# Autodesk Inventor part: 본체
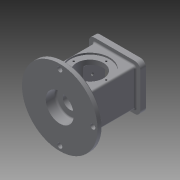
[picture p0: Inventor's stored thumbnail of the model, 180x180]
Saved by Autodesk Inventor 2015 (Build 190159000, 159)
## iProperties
Created: 2019-08
Part Number: 본체
Material: 일반
Document SubType Name: Modeling
Designer: a3
Density: 1 g/cm^3
Appearance: 기본값
Author: a3
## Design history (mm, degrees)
sketch "스케치1"
  geometry: L1 (37, 33)-(-37, 33); L2 (-37, 33)-(-37, -33); L3 (-37, -33)-(37, -33); L4 (37, -33)-(37, 33); 1 further point
  constraints: 8 end point, 2 parallel, 1 horizontal, 1 perpendicular
  dimensions: "d0" = 66 distance of L3.end L1.start; "d1" = 74 distance of L1.start L1.end; "d3" = 37 distance from line of point (0, 0) L4; "d15" = 33 distance from line of point (0, 0) L3
extrude "돌출1" new body sketch "스케치1" stored distance "d4" = 108; taper "d5" = 0 deg
sketch "스케치2"
  geometry: L1 (37, 33)-(-37, 33) reference; L2 (-37, 33)-(-37, -33) reference; L3 (-37, -33)-(37, -33) reference; L4 (37, -33)-(37, 33) reference; C1 r 67.5 at (0, 0); 1 further point
  constraints: 1 centre point, 1 coincident
  dimensions: "d6" = 135 diameter of C1
extrude "돌출2" join sketch "스케치2" distance "d7" = 10; taper "d8" = 0 deg
sketch "스케치3"
  geometry: L1 (-46, 41)-(46, 41); L2 (46, 41)-(46, -41); L3 (46, -41)-(-46, -41); L4 (-46, -41)-(-46, 41); L5 (-37, -33)-(37, -33) reference; L6 (37, -33)-(37, 33) reference; L7 (37, 33)-(-37, 33) reference; L8 (-37, 33)-(-37, -33) reference; 1 further point
  constraints: 8 end point, 2 parallel, 1 horizontal, 1 perpendicular
  dimensions: "d9" = 92 distance of L1.start L1.end; "d10" = 82 distance of L3.end L1.start; "d11" = 46 distance from line of point (0, 0) L4; "d12" = 41 distance from line of point (0, 0) L1
extrude "돌출3" join sketch "스케치3" distance "d13" = 10; taper "d14" = 0 deg
sketch "스케치4"
  geometry: C1 r 25 at (0, 0); 1 further point
  constraints: 1 centre point, 1 coincident
  dimensions: "d16" = 50 diameter of C1
extrude "돌출4" cut sketch "스케치4" distance "d17" = 18; taper "d18" = 0 deg
sketch "스케치5"
  geometry: C1 r 12.5 at (0, 0); 1 further point
  constraints: 1 centre point, 1 coincident
  dimensions: "d19" = 25 diameter of C1
extrude "돌출5" cut sketch "스케치5" stored distance "d20" = 18; taper "d21" = 0 deg
sketch "스케치6"
  geometry: L1 (-46, 41)-(46, 41) reference; L2 (-46, -41)-(-46, 41) reference; L3 (46, -41)-(-46, -41) reference; L4 (46, 41)-(46, -41) reference; L5 (26, 26)-(-26, 26); L6 (-26, 26)-(-26, -26); L7 (-26, -26)-(26, -26); L8 (26, -26)-(26, 26); C1 r 12.5 at (0, 0) reference; 1 further point
  constraints: 8 end point, 2 parallel, 1 horizontal, 1 perpendicular
  dimensions: "d22" = 52 distance of L7.end L5.start; "d23" = 52 distance of L5.start L5.end; "d24" = 26 distance from line of point (0, 0) L8; "d25" = 26 distance from line of point (0, 0) L5
extrude "돌출6" cut sketch "스케치6" distance "d26" = 8; taper "d27" = 0 deg
sketch "스케치7"
  geometry: L1 (-26, 26)-(26, 26) reference; L2 (-26, -26)-(-26, 26) reference; L3 (26, -26)-(-26, -26) reference; L4 (26, 26)-(26, -26) reference; L5 (22, 22)-(-22, 22); L6 (-22, 22)-(-22, -22); L7 (-22, -22)-(22, -22); L8 (22, -22)-(22, 22); C1 r 12.5 at (0, 0) reference; 1 further point
  constraints: 8 end point, 2 parallel, 1 horizontal, 1 perpendicular
  dimensions: "d28" = 44 distance of L7.end L5.start; "d29" = 44 distance of L5.start L5.end; "d30" = 22 distance from line of point (0, 0) L5; "d31" = 22 distance from line of L8 point (0, 0)
extrude "돌출7" cut sketch "스케치7" distance "d32" = 74; taper "d33" = 0 deg
node "작업 평면1"
sketch "스케치9"
  geometry: C1 r 59 at (0, 0); 1 further point
  constraints: 1 centre point, 1 coincident, 1 other
  dimensions: "d36" = 118 diameter of C1
feature "엠보싱1" sketch "스케치9" dims "d0" = 66, "d1" = 74, "d3" = 37, "d15" = 33, "d37" = 0.5, "d38" = 0
sketch "스케치11"
  geometry: C1 r 35 at (37, 44); 1 further point
  constraints: 1 centre point, 1 coincident
  dimensions: "d39" = 70 diameter of C1
extrude "돌출8" cut sketch "스케치11" distance "d40" = 3; taper "d41" = 0 deg
sketch "스케치12"
  geometry: C1 r 24 at (0, 0); 1 further point
  constraints: 1 centre point, 1 coincident
  dimensions: "d42" = 48 diameter of C1
extrude "돌출9" cut sketch "스케치12" stored distance "d43" = 8; taper "d44" = 0 deg
sketch "스케치13"
  geometry: C1 r 35 at (37, 44); 1 further point
  constraints: 1 centre point, 1 coincident
  dimensions: "d45" = 70 diameter of C1
extrude "돌출10" cut sketch "스케치13" distance "d46" = 3; taper "d47" = 0 deg
sketch "스케치14"
  geometry: L1 (100.5, -10)-(-34.5, -10) reference; 3 further points
  constraints: 2 vertical alignment
  dimensions: "d48" = 37 distance from line of L1 point (33, 27); "d49" = 43 distance of point (33, 27) point (33, 70)
hole "구멍1" sketch "스케치14" at (33, 70), (33, 27) diameter "d50" = 4.917; stored, may be unused: countersink angle "d54" = 90 deg, drill point angle "d56" = 118 deg; dims "d51" = 30, "d52" = 4, "d53" = 2, "d55" = 39.6
fillet "모깎기1" dims "d57" = 10
sketch "스케치16"
  geometry: L1 (-26, -26)-(-26, 26) reference; L2 (-26, 26)-(26, 26) reference; L3 (26, 26)-(26, -26) reference; L4 (26, -26)-(-26, -26) reference; L5 (-46, -31)-(-46, 31) reference; L6 (36, -41)-(-36, -41) reference; L7 (46, 31)-(46, -31) reference; L8 (-36, 41)-(36, 41) reference; A1 r 10 centre (-36, 31) between (-36, 41) and (-46, 31) reference; A2 r 10 centre (-36, -31) between (-46, -31) and (-36, -41) reference; A3 r 10 centre (36, -31) between (36, -41) and (46, -31) reference; A4 r 10 centre (36, 31) between (46, 31) and (36, 41) reference; 5 further points
  constraints: 4 coincident
hole "구멍2" sketch "스케치16" at (-36, -31), (-36, 31), (36, 31), (36, -31) diameter "d58" = 3.242; stored, may be unused: countersink angle "d62" = 90 deg, drill point angle "d64" = 118 deg; dims "d59" = 4, "d60" = 4, "d61" = 2, "d63" = 6
sketch "스케치17"
  geometry: A1 r 29 centre (0, 0) between (0, 29) and (-29, 0); 3 further points
  constraints: 4 point on circle, 2 horizontal alignment, 2 vertical alignment, 1 centre point, 1 coincident
  dimensions: "d65" = 58 diameter of A1
hole "구멍3" sketch "스케치17" at (0, 29), (-29, 0), (0, -29), (29, 0) diameter "d66" = 3.242; stored, may be unused: countersink angle "d70" = 90 deg, drill point angle "d72" = 118 deg; dims "d67" = 4, "d68" = 4, "d69" = 2, "d71" = 6
sketch "스케치18"
  geometry: A1 r 59 centre (0, 0) between (59, 0) and (0, 59); 2 further points
  constraints: 3 point on circle, 2 vertical alignment, 1 centre point, 1 coincident, 1 horizontal alignment
  dimensions: "d73" = 118 diameter of A1
hole "구멍4" sketch "스케치18" at (59, 0), (0, 59), (0, -59) diameter "d74" = 9; stored, may be unused: countersink angle "d78" = 90 deg, drill point angle "d80" = 118 deg; dims "d75" = 4, "d76" = 4, "d77" = 2, "d79" = 6
chamfer "모따기1" distance "d81" = 3; stored, may be unused: second distance "d82" = 2, angle "d83" = 45 deg
fillet "모깎기2" dims "d84" = 3
fillet "모깎기3" dims "d85" = 3
fillet "모깎기4" dims "d86" = 3
fillet "모깎기5" dims "d87" = 3
fillet "모깎기6" dims "d88" = 3
fillet "모깎기7" dims "d89" = 3
chamfer "모따기2" distance "d90" = 1; stored, may be unused: second distance "d91" = 2, angle "d92" = 45 deg
node "솔리드1"
mirror "대칭1"
node "투영된 루프1"
node "투영된 루프2"
node "투영된 루프3"
node "투영된 루프4"
node "투영된 루프6"
other parameters: "d35" = 88
